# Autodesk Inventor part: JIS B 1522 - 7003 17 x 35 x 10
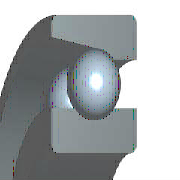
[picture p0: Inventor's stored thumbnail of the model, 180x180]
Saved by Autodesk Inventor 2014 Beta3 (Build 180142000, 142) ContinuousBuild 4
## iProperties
IsCustomPart: 0
Created: 2012-11
Part Number: JIS B 1522 - 7003 17 x 35 x 10
Material: Steel, Mild
Description: Angular Contact Ball Bearing
Document SubType Name: Modeling
Standard: JIS B 1522
Designer: Thomas
Standards Organization: JIS
Language: en-US
Size Designation: 7003 17 x 35 x 10
Categories: <MemberInstance><Categories><Category DisplayName="Shaft Parts" InternalName="7f7aeb1f-a693-4053-b835-cee3144e0d98" Mnemonic="SHFT"><Category DisplayName="Beari
Density: 1 g/cm^3
Appearance: Steel
Author: Thomas
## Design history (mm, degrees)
sketch "Sketch" dims "d1" = 4.68 (= -0.26 x WD + 0.26 x BD)
  geometry: L1 (2.66, 13)-(7.34, 13); L2 (5, 15.34)-(5, 10.66); L3 (0, 11.434)-(3.261, 11.434); L4 (0, 8.5)-(10, 8.5); L5 (5.406, 15.304)-(0, 16.258); L6 (10, 11.434)-(10, 8.5); L7 (10, 11.434)-(6.739, 11.434); L8 (10, 14.566)-(6.739, 14.566); L9 (10, 14.566)-(10, 17.5); L10 (0, 17.5)-(10, 17.5); L11 (-2.4, 0)-(14.4, 0) reference; L12 (0, -1.44)-(0, 8.99) reference; 1 further point
  constraints: 20 end point, 4 point on line, 3 symmetric about line, 2 midpoint, 2 parallel, 1 perpendicular, 14 other
  dimensions: "d0" = 10 deg angle of L8 L5; "d11" = 17 diameter of L4 L11 (= WD); "d12" = 35 diameter of L10 L11 (= BD); "d13" = 10 distance between parallel lines of L6 L12 (= KB); "d14" = 22.868 diameter of L7 L11 (= 0.326 x BD + 0.674 x WD)
revolve "Body" stored, may be unused: angle "d6" = 90 deg
revolve "Ball" stored, may be unused: angle "d8" = 90 deg
pattern_circular "Balls" dims angle "d4" = 360 deg
body "Solid1"
fillet "Fillet1" dims "d2" = 0.3 (= KRS)
other parameters: "WD" = 17 [user parameter; used in 5 equation terms], "BD" = 35 [user parameter; used in 5 equation terms], "KB" = 10 [user parameter; used in 1 equation term], "KRS" = 0.3 [user parameter; used in 1 equation term], "d5" = 0, "d7" = 0, "d9" = 0, "d15" = 0, "d16" = 0, "BC0" = 5500000 [user parameter], "BBA" = 20 deg [user parameter], "BC" = 1e+07 [user parameter], "KR1S" = 0.15 [user parameter], "BR" = 17.5 (= 0.5 x BD) [user parameter], "WR" = 8.5 (= 0.5 x WD) [user parameter]
